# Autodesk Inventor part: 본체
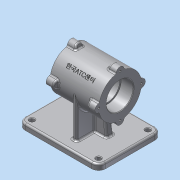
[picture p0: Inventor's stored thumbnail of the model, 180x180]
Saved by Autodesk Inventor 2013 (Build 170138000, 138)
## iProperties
Created: 2015-12
Part Number: 본체
Material: 알루미늄 6061
Document SubType Name: Modeling
Designer: dgall
Mass: 1164.73 g
Surface Area: 816.578 cm^2
Volume: 429.79 cm^3
Density: 2.71 g/cm^3
Author: dgall
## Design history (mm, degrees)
sketch "스케치1"
  geometry: L1 (0, 0)-(140, 0); L2 (140, 0)-(140, 10); L3 (140, 10)-(0, 10); L4 (0, 10)-(0, 0); L5 (37.5, 80)-(122.5, 80); L6 (122.5, 80)-(122.5, 117); L7 (37.5, 117)-(37.5, 80); L8 (37.5, 117)-(122.5, 117); L9 (37.5, 103.5)-(59.5, 103.5); L10 (59.5, 103.5)-(59.5, 101); L11 (59.5, 101)-(100.5, 101); L12 (100.5, 101)-(100.5, 103.5); L13 (100.5, 103.5)-(122.5, 103.5)
  constraints: 26 end point, 6 parallel, 6 perpendicular, 2 equal length, 2 point on line, 1 horizontal
  dimensions: "d0" = 140 distance of L2.end L3.end; "d2" = 10 distance of L3.end L1.start; "d3" = 80 distance between parallel lines of L5 L1; "d4" = 74 diameter of L8 L5; "d5" = 85 distance of L7.start L6.end; "d6" = 37.5 distance between parallel lines of L7 L4; "d7" = 42 diameter of L11 L5; "d8" = 47 diameter of L13 L5; "d9" = 22 distance of L9.start L9.end
revolve "회전1" stored, may be unused: angle "d10" = 90 deg
extrude "돌출1" join sketch "스케치1" stored distance "d11" = 110; taper "d12" = 0 deg
sketch "스케치2"
  geometry: L1 (0, 110)-(0, 0) reference; L2 (140, 110)-(140, 0) reference; L3 (0, 110)-(140, 110) reference; L4 (76, 92)-(76, 61); L5 (76, 61)-(55, 61); L6 (55, 61)-(55, 49); L7 (55, 49)-(76, 49); L8 (76, 49)-(76, 18); L9 (76, 18)-(84, 18); L10 (84, 18)-(84, 49); L11 (84, 49)-(105, 49); L12 (105, 49)-(105, 61); L13 (105, 61)-(84, 61); L14 (84, 61)-(84, 92); L15 (84, 92)-(76, 92); 4 further points
  constraints: 24 end point, 8 parallel, 6 equal length, 3 midpoint, 2 collinear, 2 perpendicular, 1 horizontal alignment
  dimensions: "d13" = 8 distance of L14.end L4.start; "d15" = 12 distance of L11.end L12.end; "d16" = 50 distance between parallel lines of L12 L6; "d17" = 74 distance between parallel lines of L9 L15; "d18" = 80 distance from line of point (80, 92) L1
extrude "돌출2" join sketch "스케치2" stored distance "d19" = 0; taper "d20" = 0 deg
sketch "스케치5"
  geometry: L1 (0, 110)-(140, 110) reference; 2 further points
  dimensions: "d30" = 12 horizontal distance of point (12, 98) L1.start; "d31" = 12 distance from line of point (12, 98) L1
hole "구멍1" sketch "스케치5" at (12, 98) diameter "d32" = 8; stored, may be unused: countersink angle "d36" = 90 deg, drill point angle "d38" = 0 deg; dims "d33" = 6, "d34" = 4, "d35" = 2, "d37" = 8
chamfer "모따기1" distance "d39" = 1; stored, may be unused: second distance "d40" = 2, angle "d41" = 45 deg
fillet "모깎기1" dims "d48" = 12
fillet "모깎기2" dims "d49" = 3
fillet "모깎기6" dims "d53" = 0.3
chamfer "모따기2" distance "d54" = 1; stored, may be unused: second distance "d55" = 2, angle "d56" = 45 deg
feature "면 기울기5" dims angle "d97" = 7 deg
feature "면 기울기6" dims angle "d98" = 7 deg
fillet "모깎기13" dims "d99" = 3
fillet "모깎기14" dims "d100" = 3
node "작업축1"
node "작업 평면3"
feature "엠보싱1" dims "d0" = 140, "d2" = 10, "d3" = 80, "d4" = 74, "d5" = 85, "d6" = 37.5, "d7" = 42, "d8" = 47, "d9" = 22, "d103" = 0.5, "d104" = 0
sketch "스케치6"
  geometry: L1 (-7, 30)-(7, 30); L2 (7, 30)-(7, 44); L3 (7, 44)-(-7, 44); L4 (-7, 44)-(-7, 30); A1 r 7 centre (0, 37) between (7, 37) and (0, 44); 4 further points
  constraints: 8 end point, 4 midpoint, 4 point on circle, 2 parallel, 2 vertical alignment, 1 centre point, 1 horizontal, 1 perpendicular, 1 other
  dimensions: "d105" = 7 radius of A1
extrude "돌출5" join sketch "스케치6" distance "d107" = 15; taper "d108" = 0 deg
feature "면 기울기7" dims angle "d109" = 20 deg
fillet "모깎기15" dims "d110" = 7
fillet "모깎기16" dims "d111" = 3
fillet "모깎기17" dims "d112" = 3
hole "구멍4" diameter "d115" = 3.459; stored, may be unused: countersink angle "d119" = 90 deg, drill point angle "d121" = 118 deg; dims "d113" = 10, "d114" = 10, "d116" = 9, "d117" = 4, "d118" = 2, "d120" = 11
node "작업 평면4"
node "솔리드1"
pattern_linear "직사각형 패턴1" dims "d44" = 86, "d47" = 116
pattern_circular "원형 패턴3" dims "d123" = 360 deg
mirror "대칭2"
sketch "스케치7"
  geometry: L1 (42.5, -26.163)-(42.5, -26.163) reference; 3 further points
  constraints: 1 horizontal alignment, 1 point on line, 1 other
  dimensions: "d102" = 42.5 distance from line of point (0, 0) L1
